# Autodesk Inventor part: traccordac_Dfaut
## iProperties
Created: 2007-07
Part Number: traccordac_Dfaut
Document SubType Name: Modeling
Designer: EF
Density: 1 g/cm^3
Author: EF
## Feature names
1. Base1
